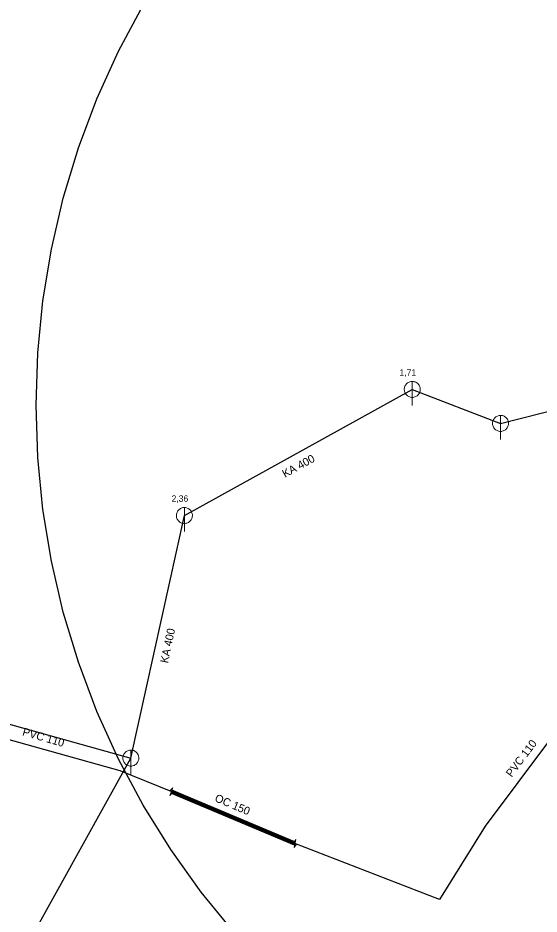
# Model space of a CAD drawing. Extents: x -724358 to -723714, y -973310 to -972026.
# Drawn here: x -724189.5 to -724124.3, y -973017.9 to -972905.9 of the extents above; entities that cross this region are included whole.
import ezdxf

# ---------------------------------------------------------------- set-up
doc = ezdxf.new("R2010")
doc.units = 0
doc.header["$LTSCALE"] = 0.4
for name, color, linetype, lineweight in [('1', 7, 'Continuous', 13), ('14', 7, 'Continuous', 13), ('17', 7, 'Continuous', 25), ('22', 7, 'Continuous', 13), ('3', 7, 'Continuous', 106), ('47', 7, 'Continuous', 13)]:
    doc.layers.add(name, color=color, linetype=linetype, lineweight=lineweight)

msp = doc.modelspace()

# ---------------------------------------------------------------- linework, layer by layer
at = {"layer": '1', "lineweight": 25}
msp.add_lwpolyline([(-724162.383, -973020.192), (-724166.535, -973015.133), (-724170.346, -973009.814), (-724173.802, -973004.257), (-724176.887, -972998.486), (-724179.587, -972992.526), (-724181.892, -972986.401), (-724183.792, -972980.139), (-724185.278, -972973.766), (-724186.344, -972967.31), (-724186.985, -972960.798), (-724187.199, -972954.257), (-724186.985, -972947.717), (-724186.344, -972941.205), (-724185.278, -972934.748), (-724183.792, -972928.375), (-724181.892, -972922.113), (-724179.587, -972915.989), (-724176.887, -972910.028), (-724173.802, -972904.257)], dxfattribs=at)
at = {"layer": '14', "lineweight": 25}
msp.add_line((-724206.69, -972989.649), (-724175.35, -972998.37), dxfattribs=at)
msp.add_lwpolyline([(-724199.68, -973042.18), (-724175.35, -972998.37), (-724168.649, -972968.05), (-724140.149, -972952.289), (-724129.112, -972956.537), (-724090.03, -972946.64), (-724084.339, -972950.81)], dxfattribs=at)
at = {"layer": '17'}
msp.add_line((-724154.829, -973009.05), (-724170.289, -973002.559), dxfattribs=at)
for points in [[(-724170.289, -973002.559), (-724176.69, -972999.98), (-724195.07, -972994.829), (-724213.21, -972990.309)], [(-724118.629, -972990.349), (-724131.039, -973006.89), (-724136.75, -973016.03), (-724154.829, -973009.05)]]:
    msp.add_lwpolyline(points, dxfattribs=at)
at = {"layer": '22'}
for p, q in [((-724140.149, -972954.289), (-724140.148, -972951.289)), ((-724129.112, -972958.537), (-724129.111, -972955.537)), ((-724168.649, -972970.05), (-724168.648, -972967.05)), ((-724175.35, -973000.37), (-724175.349, -972997.37))]:
    msp.add_line(p, q, dxfattribs=at)
for points in [[(-724139.149, -972952.289), (-724139.154, -972952.18), (-724139.172, -972952.072), (-724139.202, -972951.966), (-724139.242, -972951.865), (-724139.294, -972951.768), (-724139.356, -972951.678), (-724139.428, -972951.595), (-724139.508, -972951.521), (-724139.596, -972951.455), (-724139.69, -972951.4), (-724139.79, -972951.355), (-724139.895, -972951.322), (-724140.002, -972951.3), (-724140.111, -972951.29), (-724140.221, -972951.292), (-724140.329, -972951.306), (-724140.436, -972951.331), (-724140.539, -972951.368), (-724140.637, -972951.417), (-724140.729, -972951.475), (-724140.815, -972951.544), (-724140.892, -972951.621), (-724140.961, -972951.707), (-724141.02, -972951.799), (-724141.068, -972951.897), (-724141.105, -972952), (-724141.131, -972952.107), (-724141.145, -972952.215), (-724141.148, -972952.325), (-724141.138, -972952.434), (-724141.117, -972952.541), (-724141.083, -972952.645), (-724141.039, -972952.745), (-724140.984, -972952.84), (-724140.918, -972952.928), (-724140.844, -972953.008), (-724140.761, -972953.08), (-724140.671, -972953.142), (-724140.575, -972953.194), (-724140.473, -972953.235), (-724140.368, -972953.265), (-724140.26, -972953.283), (-724140.15, -972953.289), (-724140.041, -972953.283), (-724139.933, -972953.265), (-724139.828, -972953.236), (-724139.726, -972953.195), (-724139.629, -972953.143), (-724139.539, -972953.081), (-724139.456, -972953.01), (-724139.381, -972952.93), (-724139.316, -972952.842), (-724139.26, -972952.748), (-724139.216, -972952.648), (-724139.182, -972952.544), (-724139.16, -972952.436), (-724139.15, -972952.327)], [(-724128.112, -972956.537), (-724128.117, -972956.428), (-724128.135, -972956.32), (-724128.165, -972956.214), (-724128.205, -972956.113), (-724128.257, -972956.016), (-724128.319, -972955.926), (-724128.391, -972955.843), (-724128.471, -972955.769), (-724128.559, -972955.703), (-724128.653, -972955.648), (-724128.753, -972955.603), (-724128.858, -972955.57), (-724128.965, -972955.548), (-724129.074, -972955.538), (-724129.184, -972955.54), (-724129.292, -972955.554), (-724129.399, -972955.579), (-724129.502, -972955.616), (-724129.6, -972955.665), (-724129.692, -972955.723), (-724129.778, -972955.792), (-724129.855, -972955.869), (-724129.924, -972955.955), (-724129.983, -972956.047), (-724130.031, -972956.145), (-724130.068, -972956.248), (-724130.094, -972956.355), (-724130.108, -972956.463), (-724130.111, -972956.573), (-724130.101, -972956.682), (-724130.08, -972956.789), (-724130.046, -972956.893), (-724130.002, -972956.993), (-724129.947, -972957.088), (-724129.881, -972957.176), (-724129.807, -972957.256), (-724129.724, -972957.328), (-724129.634, -972957.39), (-724129.538, -972957.442), (-724129.436, -972957.483), (-724129.331, -972957.513), (-724129.223, -972957.531), (-724129.113, -972957.537), (-724129.004, -972957.531), (-724128.896, -972957.513), (-724128.791, -972957.484), (-724128.689, -972957.443), (-724128.592, -972957.391), (-724128.502, -972957.329), (-724128.419, -972957.258), (-724128.344, -972957.178), (-724128.279, -972957.09), (-724128.223, -972956.996), (-724128.179, -972956.896), (-724128.145, -972956.792), (-724128.123, -972956.684), (-724128.113, -972956.575)], [(-724167.649, -972968.05), (-724167.654, -972967.941), (-724167.672, -972967.833), (-724167.702, -972967.727), (-724167.742, -972967.626), (-724167.794, -972967.529), (-724167.856, -972967.439), (-724167.928, -972967.356), (-724168.008, -972967.282), (-724168.096, -972967.216), (-724168.19, -972967.161), (-724168.29, -972967.116), (-724168.395, -972967.083), (-724168.502, -972967.061), (-724168.611, -972967.051), (-724168.721, -972967.053), (-724168.829, -972967.067), (-724168.936, -972967.092), (-724169.039, -972967.129), (-724169.137, -972967.178), (-724169.229, -972967.236), (-724169.315, -972967.305), (-724169.392, -972967.382), (-724169.461, -972967.468), (-724169.52, -972967.56), (-724169.568, -972967.658), (-724169.605, -972967.761), (-724169.631, -972967.868), (-724169.645, -972967.976), (-724169.648, -972968.086), (-724169.638, -972968.195), (-724169.617, -972968.302), (-724169.583, -972968.406), (-724169.539, -972968.506), (-724169.484, -972968.601), (-724169.418, -972968.689), (-724169.344, -972968.769), (-724169.261, -972968.841), (-724169.171, -972968.903), (-724169.075, -972968.955), (-724168.973, -972968.996), (-724168.868, -972969.026), (-724168.76, -972969.044), (-724168.65, -972969.05), (-724168.541, -972969.044), (-724168.433, -972969.026), (-724168.328, -972968.997), (-724168.226, -972968.956), (-724168.129, -972968.904), (-724168.039, -972968.842), (-724167.956, -972968.771), (-724167.881, -972968.691), (-724167.816, -972968.603), (-724167.76, -972968.509), (-724167.716, -972968.409), (-724167.682, -972968.305), (-724167.66, -972968.197), (-724167.65, -972968.088)], [(-724174.35, -972998.37), (-724174.355, -972998.261), (-724174.373, -972998.153), (-724174.403, -972998.047), (-724174.443, -972997.946), (-724174.495, -972997.849), (-724174.557, -972997.759), (-724174.629, -972997.676), (-724174.709, -972997.602), (-724174.797, -972997.536), (-724174.891, -972997.481), (-724174.991, -972997.436), (-724175.096, -972997.403), (-724175.203, -972997.381), (-724175.312, -972997.371), (-724175.422, -972997.373), (-724175.53, -972997.387), (-724175.637, -972997.412), (-724175.74, -972997.449), (-724175.838, -972997.498), (-724175.93, -972997.556), (-724176.016, -972997.625), (-724176.093, -972997.702), (-724176.162, -972997.788), (-724176.221, -972997.88), (-724176.269, -972997.978), (-724176.306, -972998.081), (-724176.332, -972998.188), (-724176.346, -972998.296), (-724176.349, -972998.406), (-724176.339, -972998.515), (-724176.318, -972998.622), (-724176.284, -972998.726), (-724176.24, -972998.826), (-724176.185, -972998.921), (-724176.119, -972999.009), (-724176.045, -972999.089), (-724175.962, -972999.161), (-724175.872, -972999.223), (-724175.776, -972999.275), (-724175.674, -972999.316), (-724175.569, -972999.346), (-724175.461, -972999.364), (-724175.351, -972999.37), (-724175.242, -972999.364), (-724175.134, -972999.346), (-724175.029, -972999.317), (-724174.927, -972999.276), (-724174.83, -972999.224), (-724174.74, -972999.162), (-724174.657, -972999.091), (-724174.582, -972999.011), (-724174.517, -972998.923), (-724174.461, -972998.829), (-724174.417, -972998.729), (-724174.383, -972998.625), (-724174.361, -972998.517), (-724174.351, -972998.408)]]:
    msp.add_lwpolyline(points, close=True, dxfattribs=at)
at = {"layer": '3'}
msp.add_line((-724170.29, -973002.56), (-724154.83, -973009.05), dxfattribs=at)
at = {"layer": '3', "lineweight": 100}
msp.add_line((-724170.29, -973002.56), (-724154.83, -973009.05), dxfattribs=at)
at = {"layer": '47'}
for p, q in [((-724170.093, -973002.088), (-724170.456, -973002.447)), ((-724154.726, -973008.551), (-724155.015, -973008.972))]:
    msp.add_line(p, q, dxfattribs=at)
for points in [[(-724170.093, -973002.088), (-724170.484, -973003.029), (-724170.121, -973002.67)], [(-724154.726, -973008.551), (-724154.933, -973009.548), (-724154.644, -973009.127)]]:
    msp.add_lwpolyline(points, dxfattribs=at)

# ---------------------------------------------------------------- texts
at = {"layer": '1'}
for s, p in [('1,71', (-724141.75, -972950.578)), ('2,36', (-724170.25, -972966.338))]:
    msp.add_text(s, height=0.8, dxfattribs=at).set_placement(p)
for s, rotation, p in [('KA 400', 29, (-724156.064, -972963.358)), ('KA 400', 78, (-724170.708, -972986.567)), ('PVC 110 ', 344, (-724188.984, -972995.511)), ('PVC 110 ', 53, (-724127.722, -973000.827)), ('OC 150', 337, (-724164.944, -973003.734))]:
    msp.add_text(s, height=1, rotation=rotation, dxfattribs=at).set_placement(p)

doc.saveas('drawing.dxf')
